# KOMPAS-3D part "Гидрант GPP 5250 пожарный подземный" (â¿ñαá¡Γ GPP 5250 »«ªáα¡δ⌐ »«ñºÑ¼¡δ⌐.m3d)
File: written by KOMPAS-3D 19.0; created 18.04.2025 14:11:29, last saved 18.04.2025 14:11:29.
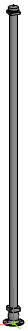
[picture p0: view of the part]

Document properties: Полное имя файла: E:\Dendor Работа Сачек\3D для проекитирвщиков\11.1 Тип GPP. Гидрант пожарный подземный\stp_Тип GPP. 750-6000 Гидрант пожарный подземный\Гидрант GPP 5250 пожарный подземный.m3d

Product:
- Part/product: Гидрант GPP 5250 пожарный подземный

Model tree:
1. Операция без истории:1  (labels: Гидрант GPP 5250 пожарный подземный)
